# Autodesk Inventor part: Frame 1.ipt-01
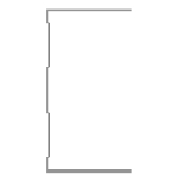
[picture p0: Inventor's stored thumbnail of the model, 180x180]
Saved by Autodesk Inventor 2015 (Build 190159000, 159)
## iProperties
_CCFamilyMember: 1
_CCFamilyDisplayName: Kévin - Kévin Novo
_FrameMemberDoc: Frame Member File
_Version: 15.0.0
_GetPNFromCC: 1
Created: 2015-04
Part Number: Frame 1.ipt-01
Material: Aluminum 6061
Description: Kévin Novo
Document SubType Name: Modeling
Standard: Kevin
Designer: suporte
Standards Organization: Kevin
Language: en-US
Size Designation: (Unnamed 1)
Categories: <MemberInstance><Categories><Category DisplayName="Structural Shapes" InternalName="089c4875-fa83-4c05-b084-43b9cc11f5ed" Mnemonic="GRDR"><CategoryParameter Dis
Density: 2.7 g/cm^3
Appearance: Aluminum - Flat
IsCustomPart: 1
G_L: 1275,000 mm
G_W: 50,000 mm
G_H: 75,000 mm
+BE02B1BA-F544-4DB9-A8C6-22E0BFEE486C+CUTDETAIL1: Cut
+B7FB69BA-66C3-49F6-BE44-D662183E9D35+CUTDETAIL2: Cut
Author: suporte
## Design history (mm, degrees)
node "Start Plane"
node "End Plane"
sketch "Sketch"
  geometry: L1 (24.7, 37.5)-(24.7, 36.9); L2 (24.7, 36.9)-(-24.7, 36.9); L3 (-24.7, -36.9)-(24.7, -36.9); L4 (24.7, -36.9)-(24.7, -37.5); L5 (24.7, -37.5)-(-25.3, -37.5); L6 (-25.3, 37.5)-(24.7, 37.5); L7 (-24.7, 36.9)-(-24.7, 31.9); L8 (-24.7, 31.9)-(-23.3, 30.5); L9 (-23.3, 30.5)-(-23.3, 10.934); L10 (-23.3, 10.934)-(-24.7, 9.534); L11 (-24.7, 9.534)-(-24.7, -9.534); L12 (-24.7, -9.534)-(-23.3, -10.934); L13 (-23.3, -10.934)-(-23.3, -30.5); L14 (-23.3, -30.5)-(-24.7, -31.9); L15 (-24.7, -31.9)-(-24.7, -36.9); L16 (-25.3, -37.5)-(-25.3, -31.651); L17 (-25.3, -31.651)-(-23.9, -30.251); L18 (-23.9, -30.251)-(-23.9, -11.183); L19 (-23.9, -11.183)-(-25.3, -9.783); L20 (-25.3, -9.783)-(-25.3, 9.783); L21 (-25.3, 9.783)-(-23.9, 11.183); L22 (-23.9, 11.183)-(-23.9, 30.251); L23 (-23.9, 30.251)-(-25.3, 31.651); L24 (-25.3, 31.651)-(-25.3, 37.5); L25 (-25.3, 0)-(30.37, 0); 3 further points
  constraints: 50 end point, 10 point on line, 9 parallel, 5 perpendicular, 4 equal length, 3 midpoint, 3 vertical, 2 vertical alignment, 1 collinear, 1 horizontal, 1 horizontal alignment
  dimensions: "d3" = 0.6 distance of L1.start L1.end (= d6); "d5" = 75 distance between parallel lines of L5 L6; "d6" = 0.6 distance between parallel lines of L24 L7 (= d8); "d7" = 0.6 distance between parallel lines of L8 L23 (= d8); "d8" = 0.6 distance between parallel lines of L22 L9 (= d12); "Espessura" = 0.6 distance between parallel lines of L17 L14; "d10" = 0.6 distance between parallel lines of L13 L18 (= Espessura); "d11" = 0.6 distance between parallel lines of L12 L19 (= Espessura); "d12" = 0.6 distance between parallel lines of L21 L10 (= d11); "d13" = 5 distance of L2.end L7.end; "d15" = 135 deg angle of L9 L8; "d16" = 2 distance between parallel lines of L24 L9; "d17" = 50 distance of L6.start L1.start
extrude "Body" join sketch "Sketch" stored distance "d24" = 0.13; taper "d25" = 0 deg
node "Driven Length"
  sketch "Sketch10"
    geometry: L1 (0, 0)-(10, 0) reference
    constraints: 2 end point, 1 horizontal
  workplane "Work Plane7"
  sketch "Sketch11"
    geometry: L1 (-2, -87.5)-(12, -87.5) reference; L2 (-2, 1187.5)-(12, 1187.5) reference
    dimensions: "d27" = 1275 distance between parallel lines of L1 L2 (derived)
workplane "Work Plane8"
split "Split1"
workplane "Work Plane9"
split "Split2"
body "Solid1"
other parameters: "G_OFFSET_START" = 87.5 [user parameter; used in 1 equation term], "G_OFFSET_END" = -12.5 [user parameter; used in 1 equation term], "d22" = -87.5 (= -G_OFFSET_START), "d23" = 1187.5 (= tamanho + G_OFFSET_END), "G_L" = 1275 (= d27) [user parameter], "d34" = 90 deg
